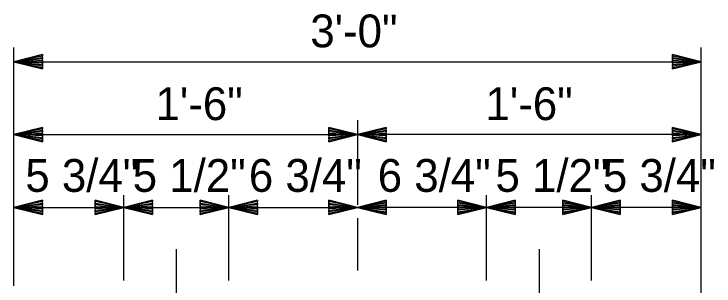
# Model space of a CAD drawing. Extents: x 0 to 177, y -1 to 130.
# Drawn here: x 50.766 to 53.822, y 17.602 to 18.788 of the extents above; entities that cross this region are included whole.
import ezdxf

# ---------------------------------------------------------------- set-up
doc = ezdxf.new("R2010")
doc.units = 0
for name, color, linetype in [('Dimension Lines', 7, 'Continuous'), ('Mis Center Lines', 7, 'Continuous'), ('Text', 7, 'Continuous')]:
    doc.layers.add(name, color=color, linetype=linetype)

msp = doc.modelspace()

# ---------------------------------------------------------------- linework, layer by layer
at = {"layer": 'Dimension Lines'}
for p, q in [((50.7662, 17.6029), (50.7662, 18.6421)), ((53.7662, 17.0576), (53.7662, 18.6421)), ((50.7662, 18.5796), (53.7662, 18.5796)), ((50.7662, 18.2622), (52.2662, 18.2622)), ((53.7662, 18.2622), (52.2662, 18.2622)), ((51.2454, 17.6251), (51.2454, 17.998)), ((51.7037, 17.6251), (51.7037, 17.998)), ((52.8287, 17.6251), (52.8287, 17.998)), ((53.2871, 17.6251), (53.2871, 17.998)), ((50.7662, 17.9445), (51.2454, 17.9445)), ((51.2454, 17.9445), (51.7037, 17.9445)), ((51.7037, 17.9445), (52.2662, 17.9445)), ((52.8287, 17.9445), (52.2662, 17.9445)), ((53.2871, 17.9445), (52.8287, 17.9445)), ((53.7662, 17.9445), (53.2871, 17.9445))]:
    msp.add_line(p, q, dxfattribs=at)
for points in [[(50.8912, 18.5796), (50.8912, 18.5733), (50.7662, 18.5796), (50.8912, 18.5671), (50.8912, 18.5608), (50.7662, 18.5796), (50.8912, 18.5546), (50.8912, 18.5483), (50.7662, 18.5796), (50.8912, 18.6108), (50.8912, 18.6046), (50.7662, 18.5796), (50.8912, 18.5983), (50.8912, 18.5921), (50.7662, 18.5796), (50.8912, 18.5858), (50.8912, 18.5483), (50.8912, 18.6108), (50.7662, 18.5796), (50.8912, 18.5483)], [(53.6412, 18.5796), (53.6412, 18.5858), (53.7662, 18.5796), (53.6412, 18.5921), (53.6412, 18.5983), (53.7662, 18.5796), (53.6412, 18.6046), (53.6412, 18.6108), (53.7662, 18.5796), (53.6412, 18.5483), (53.6412, 18.5546), (53.7662, 18.5796), (53.6412, 18.5608), (53.6412, 18.5671), (53.7662, 18.5796), (53.6412, 18.5733), (53.6412, 18.6108), (53.6412, 18.5483), (53.7662, 18.5796), (53.6412, 18.6108)], [(50.8912, 18.2622), (50.8912, 18.2559), (50.7662, 18.2622), (50.8912, 18.2497), (50.8912, 18.2434), (50.7662, 18.2622), (50.8912, 18.2372), (50.8912, 18.2309), (50.7662, 18.2622), (50.8912, 18.2934), (50.8912, 18.2872), (50.7662, 18.2622), (50.8912, 18.2809), (50.8912, 18.2747), (50.7662, 18.2622), (50.8912, 18.2684), (50.8912, 18.2309), (50.8912, 18.2934), (50.7662, 18.2622), (50.8912, 18.2309)], [(52.1412, 18.2622), (52.1412, 18.2684), (52.2662, 18.2622), (52.1412, 18.2747), (52.1412, 18.2809), (52.2662, 18.2622), (52.1412, 18.2872), (52.1412, 18.2934), (52.2662, 18.2622), (52.1412, 18.2309), (52.1412, 18.2372), (52.2662, 18.2622), (52.1412, 18.2434), (52.1412, 18.2497), (52.2662, 18.2622), (52.1412, 18.2559), (52.1412, 18.2934), (52.1412, 18.2309), (52.2662, 18.2622), (52.1412, 18.2934)], [(52.3912, 18.2622), (52.3912, 18.2559), (52.2662, 18.2622), (52.3912, 18.2497), (52.3912, 18.2434), (52.2662, 18.2622), (52.3912, 18.2372), (52.3912, 18.2309), (52.2662, 18.2622), (52.3912, 18.2934), (52.3912, 18.2872), (52.2662, 18.2622), (52.3912, 18.2809), (52.3912, 18.2747), (52.2662, 18.2622), (52.3912, 18.2684), (52.3912, 18.2309), (52.3912, 18.2934), (52.2662, 18.2622), (52.3912, 18.2309)], [(53.6412, 18.2622), (53.6412, 18.2684), (53.7662, 18.2622), (53.6412, 18.2747), (53.6412, 18.2809), (53.7662, 18.2622), (53.6412, 18.2872), (53.6412, 18.2934), (53.7662, 18.2622), (53.6412, 18.2309), (53.6412, 18.2372), (53.7662, 18.2622), (53.6412, 18.2434), (53.6412, 18.2497), (53.7662, 18.2622), (53.6412, 18.2559), (53.6412, 18.2934), (53.6412, 18.2309), (53.7662, 18.2622), (53.6412, 18.2934)], [(50.8912, 17.9445), (50.8912, 17.9382), (50.7662, 17.9445), (50.8912, 17.932), (50.8912, 17.9257), (50.7662, 17.9445), (50.8912, 17.9195), (50.8912, 17.9132), (50.7662, 17.9445), (50.8912, 17.9757), (50.8912, 17.9695), (50.7662, 17.9445), (50.8912, 17.9632), (50.8912, 17.957), (50.7662, 17.9445), (50.8912, 17.9507), (50.8912, 17.9132), (50.8912, 17.9757), (50.7662, 17.9445), (50.8912, 17.9132)], [(51.1204, 17.9445), (51.1204, 17.9507), (51.2454, 17.9445), (51.1204, 17.957), (51.1204, 17.9632), (51.2454, 17.9445), (51.1204, 17.9695), (51.1204, 17.9757), (51.2454, 17.9445), (51.1204, 17.9132), (51.1204, 17.9195), (51.2454, 17.9445), (51.1204, 17.9257), (51.1204, 17.932), (51.2454, 17.9445), (51.1204, 17.9382), (51.1204, 17.9757), (51.1204, 17.9132), (51.2454, 17.9445), (51.1204, 17.9757)], [(51.3704, 17.9445), (51.3704, 17.9382), (51.2454, 17.9445), (51.3704, 17.932), (51.3704, 17.9257), (51.2454, 17.9445), (51.3704, 17.9195), (51.3704, 17.9132), (51.2454, 17.9445), (51.3704, 17.9757), (51.3704, 17.9695), (51.2454, 17.9445), (51.3704, 17.9632), (51.3704, 17.957), (51.2454, 17.9445), (51.3704, 17.9507), (51.3704, 17.9132), (51.3704, 17.9757), (51.2454, 17.9445), (51.3704, 17.9132)], [(51.5787, 17.9445), (51.5787, 17.9507), (51.7037, 17.9445), (51.5787, 17.957), (51.5787, 17.9632), (51.7037, 17.9445), (51.5787, 17.9695), (51.5787, 17.9757), (51.7037, 17.9445), (51.5787, 17.9132), (51.5787, 17.9195), (51.7037, 17.9445), (51.5787, 17.9257), (51.5787, 17.932), (51.7037, 17.9445), (51.5787, 17.9382), (51.5787, 17.9757), (51.5787, 17.9132), (51.7037, 17.9445), (51.5787, 17.9757)], [(51.8287, 17.9445), (51.8287, 17.9382), (51.7037, 17.9445), (51.8287, 17.932), (51.8287, 17.9257), (51.7037, 17.9445), (51.8287, 17.9195), (51.8287, 17.9132), (51.7037, 17.9445), (51.8287, 17.9757), (51.8287, 17.9695), (51.7037, 17.9445), (51.8287, 17.9632), (51.8287, 17.957), (51.7037, 17.9445), (51.8287, 17.9507), (51.8287, 17.9132), (51.8287, 17.9757), (51.7037, 17.9445), (51.8287, 17.9132)], [(52.1412, 17.9445), (52.1412, 17.9507), (52.2662, 17.9445), (52.1412, 17.957), (52.1412, 17.9632), (52.2662, 17.9445), (52.1412, 17.9695), (52.1412, 17.9757), (52.2662, 17.9445), (52.1412, 17.9132), (52.1412, 17.9195), (52.2662, 17.9445), (52.1412, 17.9257), (52.1412, 17.932), (52.2662, 17.9445), (52.1412, 17.9382), (52.1412, 17.9757), (52.1412, 17.9132), (52.2662, 17.9445), (52.1412, 17.9757)], [(52.3912, 17.9445), (52.3912, 17.9507), (52.2662, 17.9445), (52.3912, 17.957), (52.3912, 17.9632), (52.2662, 17.9445), (52.3912, 17.9695), (52.3912, 17.9757), (52.2662, 17.9445), (52.3912, 17.9132), (52.3912, 17.9195), (52.2662, 17.9445), (52.3912, 17.9257), (52.3912, 17.932), (52.2662, 17.9445), (52.3912, 17.9382), (52.3912, 17.9757), (52.3912, 17.9132), (52.2662, 17.9445), (52.3912, 17.9757)], [(52.7037, 17.9445), (52.7037, 17.9382), (52.8287, 17.9445), (52.7037, 17.932), (52.7037, 17.9257), (52.8287, 17.9445), (52.7037, 17.9195), (52.7037, 17.9132), (52.8287, 17.9445), (52.7037, 17.9757), (52.7037, 17.9695), (52.8287, 17.9445), (52.7037, 17.9632), (52.7037, 17.957), (52.8287, 17.9445), (52.7037, 17.9507), (52.7037, 17.9132), (52.7037, 17.9757), (52.8287, 17.9445), (52.7037, 17.9132)], [(52.9537, 17.9445), (52.9537, 17.9507), (52.8287, 17.9445), (52.9537, 17.957), (52.9537, 17.9632), (52.8287, 17.9445), (52.9537, 17.9695), (52.9537, 17.9757), (52.8287, 17.9445), (52.9537, 17.9132), (52.9537, 17.9195), (52.8287, 17.9445), (52.9537, 17.9257), (52.9537, 17.932), (52.8287, 17.9445), (52.9537, 17.9382), (52.9537, 17.9757), (52.9537, 17.9132), (52.8287, 17.9445), (52.9537, 17.9757)], [(53.1621, 17.9445), (53.1621, 17.9382), (53.2871, 17.9445), (53.1621, 17.932), (53.1621, 17.9257), (53.2871, 17.9445), (53.1621, 17.9195), (53.1621, 17.9132), (53.2871, 17.9445), (53.1621, 17.9757), (53.1621, 17.9695), (53.2871, 17.9445), (53.1621, 17.9632), (53.1621, 17.957), (53.2871, 17.9445), (53.1621, 17.9507), (53.1621, 17.9132), (53.1621, 17.9757), (53.2871, 17.9445), (53.1621, 17.9132)], [(53.4121, 17.9445), (53.4121, 17.9507), (53.2871, 17.9445), (53.4121, 17.957), (53.4121, 17.9632), (53.2871, 17.9445), (53.4121, 17.9695), (53.4121, 17.9757), (53.2871, 17.9445), (53.4121, 17.9132), (53.4121, 17.9195), (53.2871, 17.9445), (53.4121, 17.9257), (53.4121, 17.932), (53.2871, 17.9445), (53.4121, 17.9382), (53.4121, 17.9757), (53.4121, 17.9132), (53.2871, 17.9445), (53.4121, 17.9757)], [(53.6412, 17.9445), (53.6412, 17.9382), (53.7662, 17.9445), (53.6412, 17.932), (53.6412, 17.9257), (53.7662, 17.9445), (53.6412, 17.9195), (53.6412, 17.9132), (53.7662, 17.9445), (53.6412, 17.9757), (53.6412, 17.9695), (53.7662, 17.9445), (53.6412, 17.9632), (53.6412, 17.957), (53.7662, 17.9445), (53.6412, 17.9507), (53.6412, 17.9132), (53.6412, 17.9757), (53.7662, 17.9445), (53.6412, 17.9132)]]:
    msp.add_lwpolyline(points, dxfattribs=at)
at = {"layer": 'Mis Center Lines'}
for p, q in [((52.2662, 18.3252), (52.2662, 17.9561)), ((52.2662, 17.8977), (52.2662, 17.6689)), ((51.4746, 17.7622), (51.4746, 16.6877)), ((53.0579, 17.7622), (53.0579, 16.6877))]:
    msp.add_line(p, q, dxfattribs=at)

# ---------------------------------------------------------------- texts
at = {"layer": 'Text'}
for s, p in [('3\'-0"', (52.0596, 18.6425)), ('1\'-6"', (51.3839, 18.3251)), ('1\'-6"', (52.8243, 18.3251)), ('5 3/4"', (50.8158, 18.0123)), ('5 1/2"', (51.2845, 18.0123)), ('6 3/4"', (51.7914, 18.0123)), ('6 3/4"', (52.3539, 18.0123)), ('5 1/2"', (52.8679, 18.0123)), ('5 3/4"', (53.3366, 18.0123))]:
    msp.add_text(s, height=0.14302, dxfattribs=at).set_placement(p)

doc.saveas('drawing.dxf')
